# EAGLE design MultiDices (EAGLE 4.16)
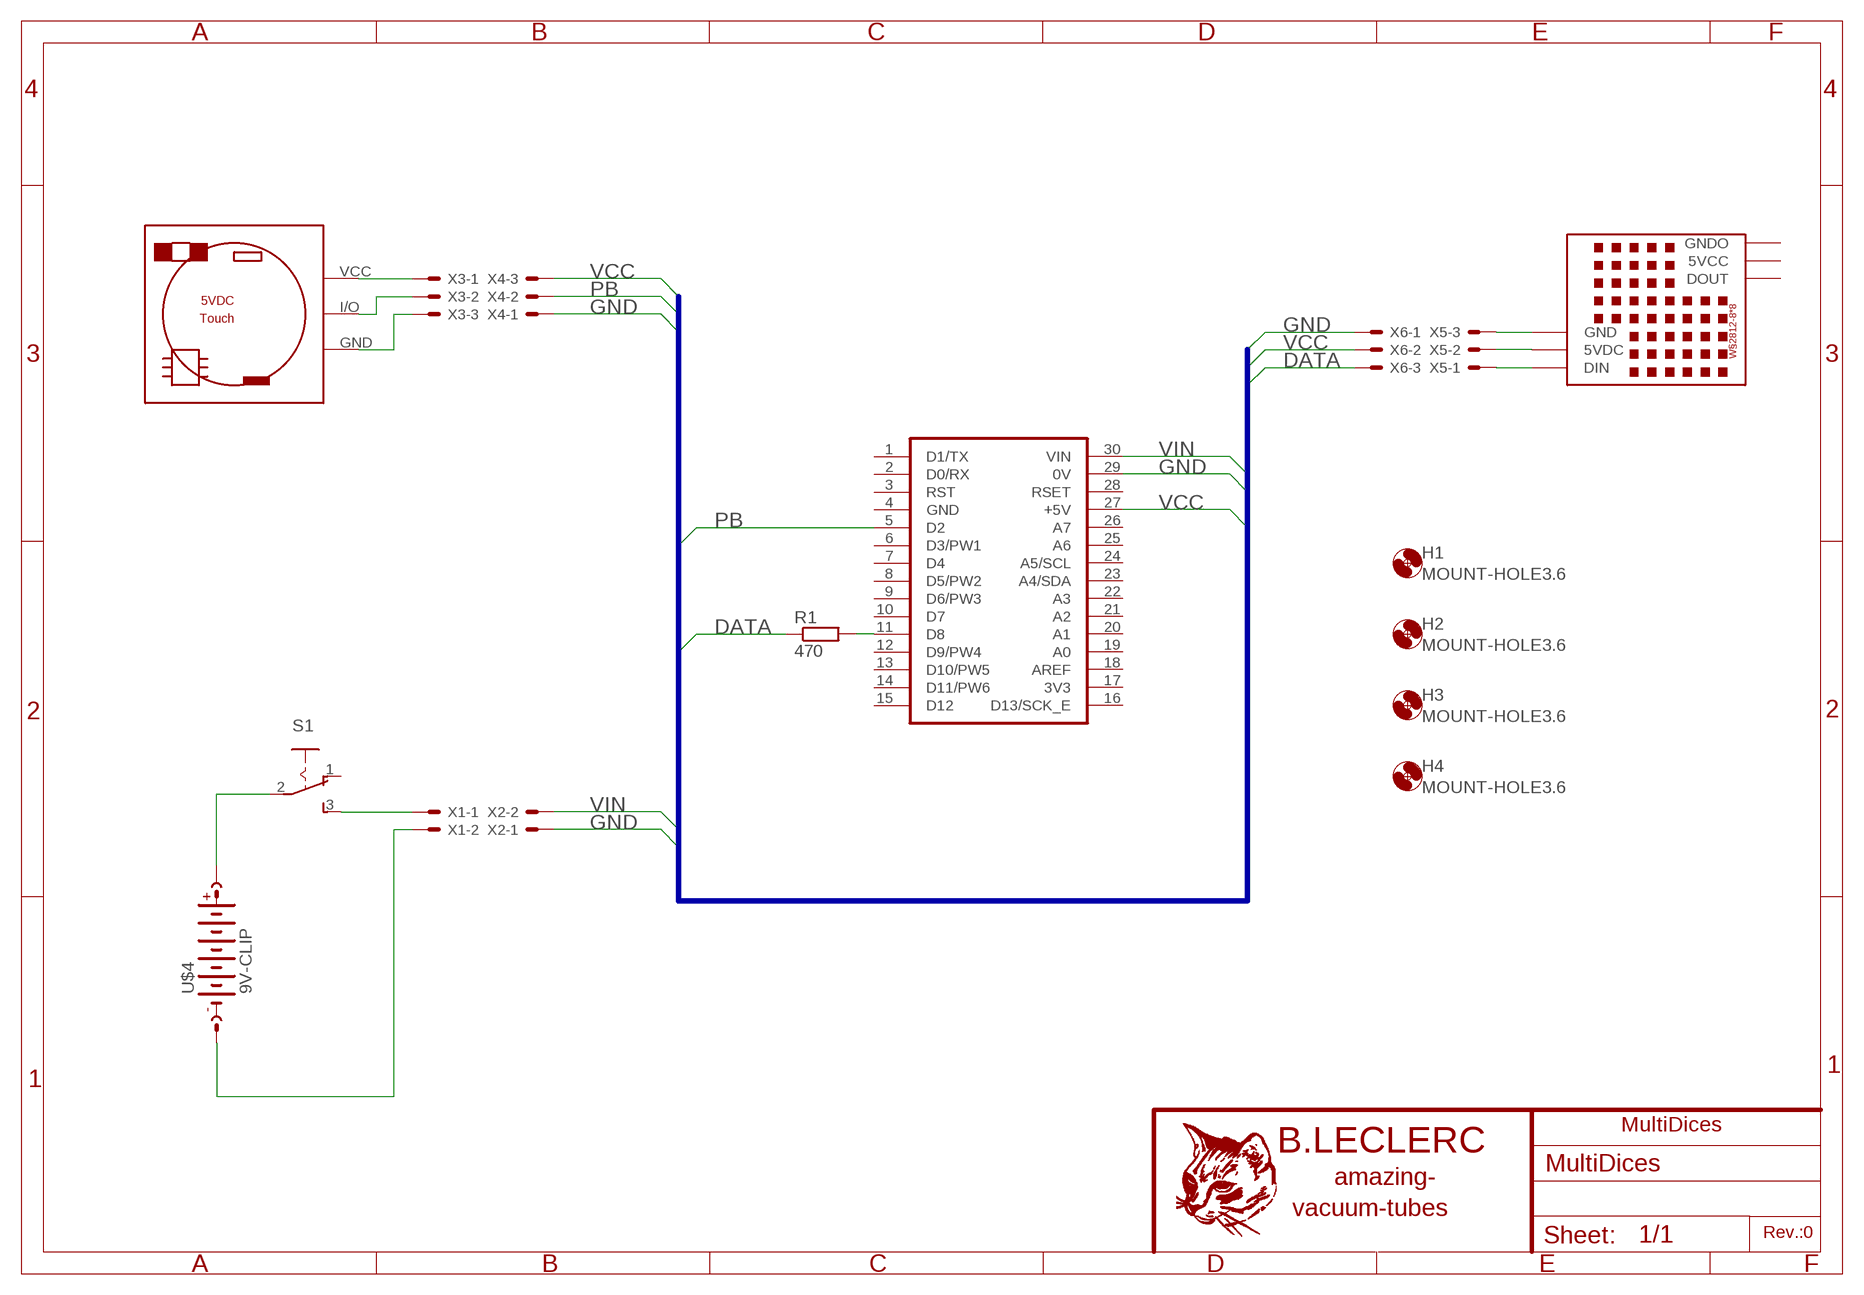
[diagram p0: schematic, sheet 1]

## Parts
H1  MOUNT-HOLE3.6  [3,6]
H2  MOUNT-HOLE3.6  [3,6]
H3  MOUNT-HOLE3.6  [3,6]
H4  MOUNT-HOLE3.6  [3,6]
R1  470  R-EU_0207/12  [0207/12]
S1  255SB  [255SB]
U1  NANO  [NANO]
U$2  64_LED_PANEL_2812-88  [64_LED_PANEL_2812-8*8]
U$3  TOUCH-BUTTON  [TOUCH-BUTTON]
U$4  9V-CLIP  [9V-CLIP]
X1  22-23-2021  [22-23-2021]
X2  22-23-2021  [22-23-2021]
X3  22-23-2031  [22-23-2031]
X4  22-23-2031  [22-23-2031]
X5  22-23-2031  [22-23-2031]
X6  22-23-2031  [22-23-2031]

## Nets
DATA: R1.1 X6.3
GND: U1.29(0V) X2.1 X4.1 X6.1
N$1: U$3.VCC X3.1
N$2: U$3.I/O X3.2
N$3: U$3.GND X3.3
N$4: S1.2(P)
N$5: S1.3(S) X1.1
N$6: R1.2 U1.11(D8)
N$7: U$2.GND X5.3
N$8: U$2.5VDC X5.2
N$9: U$2.DIN X5.1
N$10: X1.2
PB: U1.5(D2) X4.2
VCC: U1.27(+5V) X4.3 X6.2
VIN: U1.30(VIN) X2.2
Unconnected: S1.1(O) U1.1(D1/TX) U1.2(D0/RX) U1.3(RST) U1.6(D3/PW1) U1.7(D4) U1.8(D5/PW2) U1.9(D6/PW3) U1.10(D7) U1.12(D9/PW4) U1.13(D10/PW5) U1.14(D11/PW6) U1.15(D12) U1.16(D13/SCK_E) U1.18(AREF) U1.19(A0) U1.20(A1) U1.21(A2) U1.22(A3) U1.23(A4/SDA) U1.24(A5/SCL) U1.25(A6) U1.26(A7) U1.28(RSET) U$2.DOUT

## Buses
B$1

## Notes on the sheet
- MultiDices
- Rev.:0

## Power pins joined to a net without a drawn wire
3V3: U1.17(3V3)
5VCC: U$2.5VCC
GND: U1.4(GND)
GNDO: U$2.GNDO

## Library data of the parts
H1-H4 = holes:MOUNT-HOLE: MOUNTING HOLE with drill center marker
R1 = rcl:R-EU_: RESISTOR, European symbol
S1 = switch:255SB: SLIDING SWITCH distributor Buerklin, 11G810
U1 = Arduino:NANO
U$2 = Arduino:64_LED_PANEL_2812-8*8
U$3 = Arduino:TOUCH-BUTTON
U$4 = battery:9V-CLIP
X1 X2 = con-molex:22-23-2021: .100" (2.54mm) Center Header - 2 Pin
X3-X6 = con-molex:22-23-2031: .100" (2.54mm) Center Header - 3 Pin

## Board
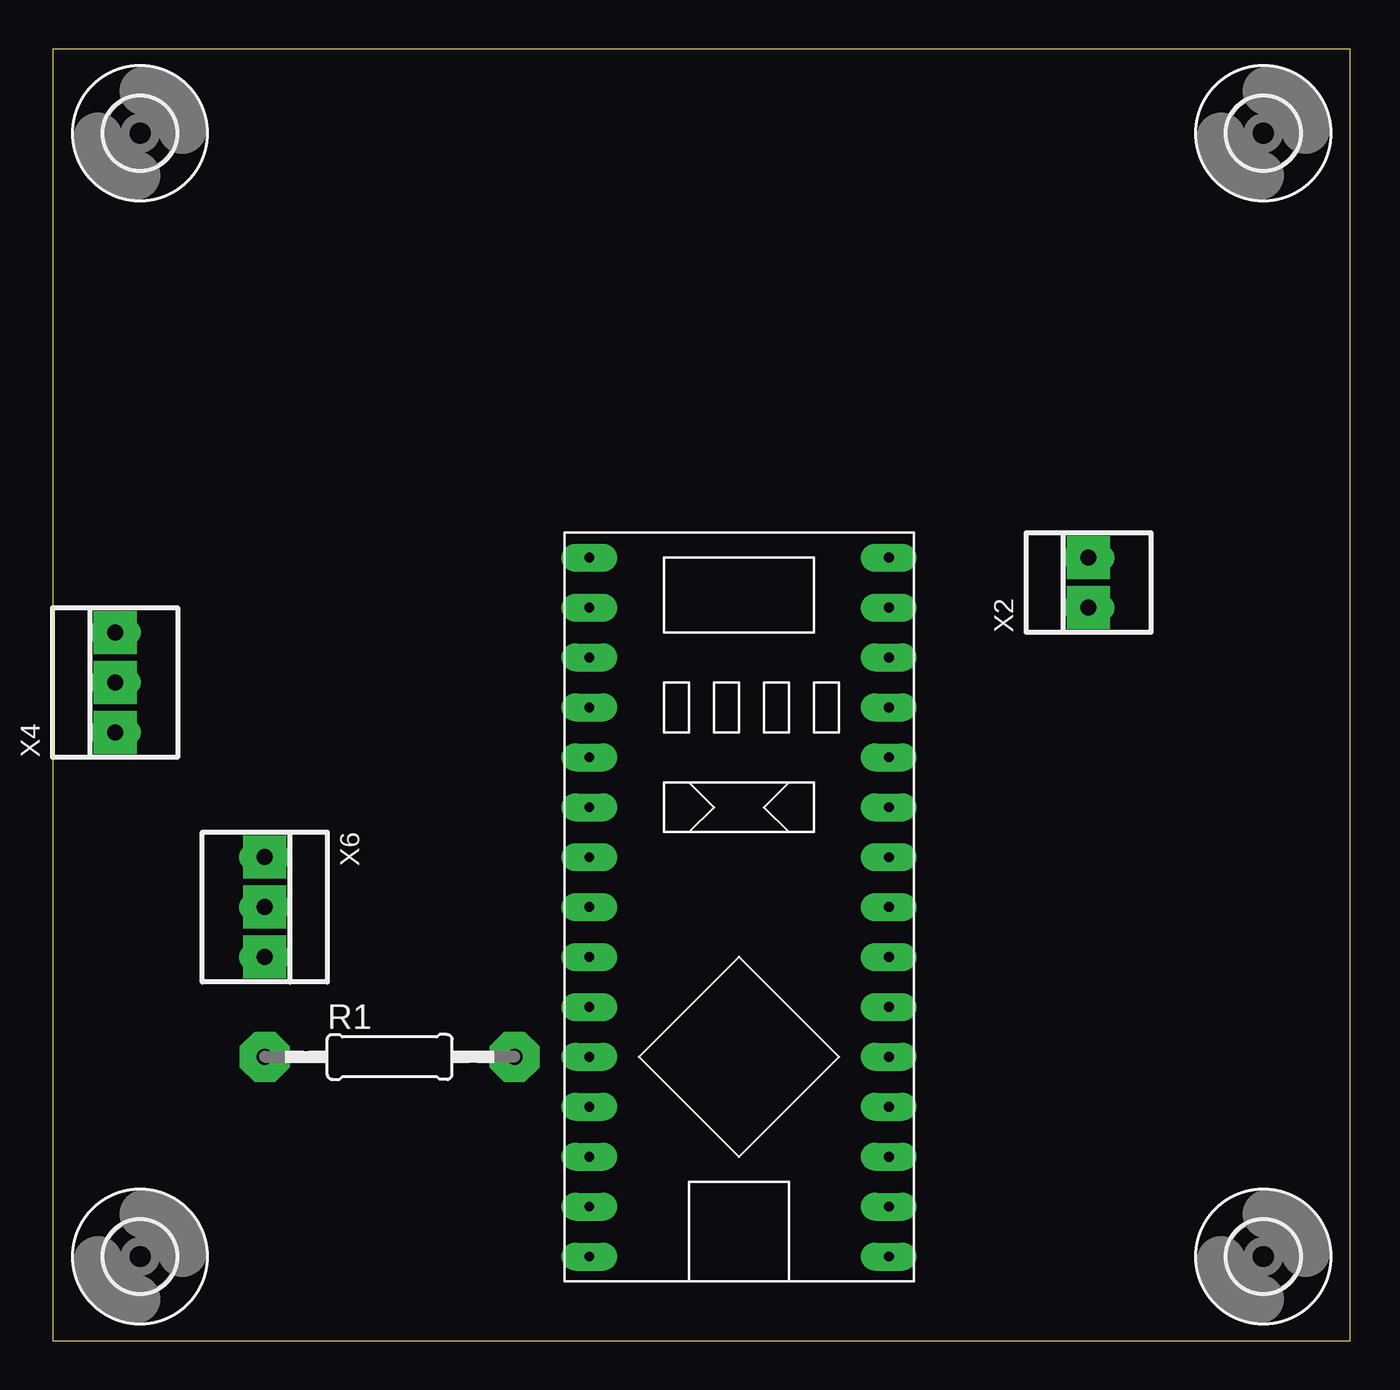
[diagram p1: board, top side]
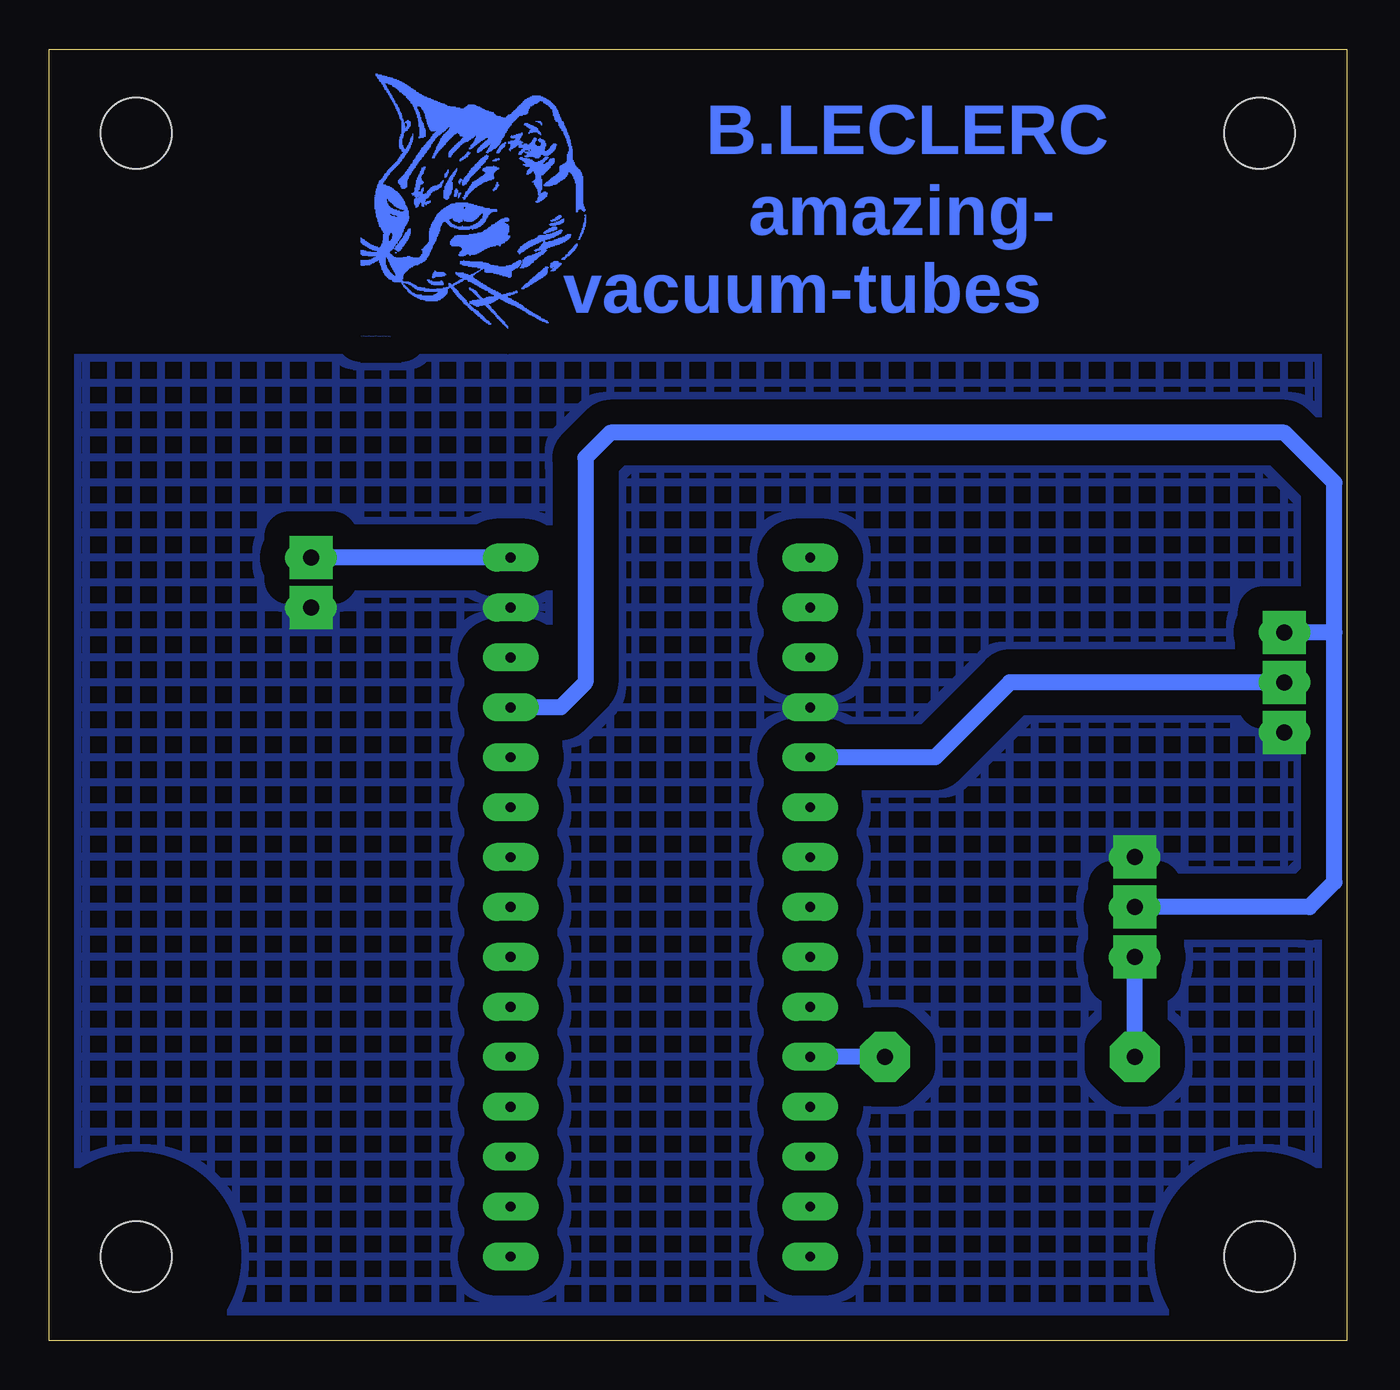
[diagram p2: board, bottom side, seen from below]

Size 66.02 x 65.71 mm. Coordinates in mm from the lower left corner, seen from the top.
Outline: 0,0 66.02,0 66.02,65.71 0,65.71 0,0
Copper layers (1*16): Top 0.035mm / dielectric 1.5mm / Bottom 0.035mm
Design rules "default": minimum track width 10mil, minimum drill 24mil, track to track 8mil, track to pad 8mil, pad to pad 8mil, via to via 8mil, smd to smd 8mil, copper to edge 40mil, drill to drill 8mil, minimum pad ring 10mil, minimum via ring 8mil, stop-mask expansion 4mil, vias tented up to drill 0mil, thermal gap 10mil

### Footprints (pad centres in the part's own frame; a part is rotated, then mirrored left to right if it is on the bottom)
3,6 = hole 3.6: 0,0
0207/12 = drill 0.813 octagon: 1 -6.35,0; 2 6.35,0
255SB = drill 1.118 long: 1 -3.81,0; 2 0,0; 3 3.81,0
NANO = drill 0.5 pad 1.422 long: 1 -7.62,17.78; 2 -7.62,15.24; 3 -7.62,12.7; 4 -7.62,10.16; 5 -7.62,7.62; 6 -7.62,5.08; 7 -7.62,2.54; 8 -7.62,0; 9 -7.62,-2.54; 10 -7.62,-5.08; 11 -7.62,-7.62; 12 -7.62,-10.16; 13 -7.62,-12.7; 14 -7.62,-15.24; 15 -7.62,-17.78; 16 7.62,-17.78; 17 7.62,-15.24; 18 7.62,-12.7; 19 7.62,-10.16; 20 7.62,-7.62; 21 7.62,-5.08; 22 7.62,-2.54; 23 7.62,0; 24 7.62,2.54; 25 7.62,5.08; 26 7.62,7.62; 27 7.62,10.16; 28 7.62,12.7; 29 7.62,15.24; 30 7.62,17.78
64_LED_PANEL_2812-8*8 = drill 0.5 pad 1.93 long: 5VCC 13.97,0; 5VDC 0,0; DIN 0,2.54; DOUT 13.97,2.54; GND 0,-2.54; GNDO 13.97,-2.54
TOUCH-BUTTON = drill 0.5 pad 1.93 square: GND 0,2.54 | drill 0.5 pad 1.93 octagon: I/O 0,0; VCC 0,-2.54
9V-CLIP = drill 0.5 pad 0.254 square: +9 7.62,-1.27; -9 7.62,-6.35
22-23-2021 = drill 0.813 long: 1 -1.27,0; 2 1.27,0
22-23-2031 = drill 0.813 long: 1 -2.54,0; 2 0,0; 3 2.54,0

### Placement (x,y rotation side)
H1  61.59,61.43 0 top
H2  61.59,4.28 0 top
H3  4.44,61.43 0 top
H4  4.44,4.28 0 top
R1  17.14,14.44 0 top
S1  not placed on the board
U1  34.92,22.06 0 top
U$2  not placed on the board
U$3  not placed on the board
U$4  not placed on the board
U$5  [CHAT1]  50.16,51.27 0 bottom
X1  not placed on the board
X2  52.7,38.57 90 top
X3  not placed on the board
X4  3.17,33.49 90 top
X5  not placed on the board
X6  10.79,22.06 270 top

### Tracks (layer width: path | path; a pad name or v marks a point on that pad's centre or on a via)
DATA
  Bottom 0.813: R1.1 X6.3
GND  (via drill 0.5 pad 2.18)
  other vias: 3.17,30.95 10.79,24.6 52.7,37.3
  pour Bottom (isolate 1.27, no thermals, hatched): 0.63,50 65.4,50 65.4,0.47 0.63,0.47
N$1  (1 unrouted)
N$2  (1 unrouted)
N$3  (1 unrouted)
N$5  (1 unrouted)
N$6
  Bottom 0.813: R1.2 U1.11
N$7  (1 unrouted)
N$8  (1 unrouted)
N$9  (1 unrouted)
N$11  (via drill 0.5 pad 2.54)
  other vias: 10.79,14.44
N$12  (via drill 0.5 pad 2.54)
  other vias: 23.49,14.44
N$13  (via drill 0.5 pad 2.18)
  other vias: 3.17,36.03
N$14  (via drill 0.5 pad 2.18)
  other vias: 3.17,33.49
N$17  (via drill 0.5 pad 2.18)
  other vias: 10.79,22.06
N$18  (via drill 0.5 pad 2.18)
  other vias: 10.79,19.52
N$19  (via drill 0.5 pad 2.18)
  other vias: 52.7,39.84
PB
  Bottom 0.813: X4.2 17.14,33.49 20.95,29.68 U1.5
VCC
  Bottom 0.813: X6.2 1.9,22.06 0.63,23.33 0.63,36.03 | 0.63,36.03 0.63,43.65 3.17,46.19 37.46,46.19 38.73,44.92 38.73,33.49 40,32.22 U1.27 | 0.63,36.03 X4.3
VIN
  Bottom 0.813: U1.30 X2.2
